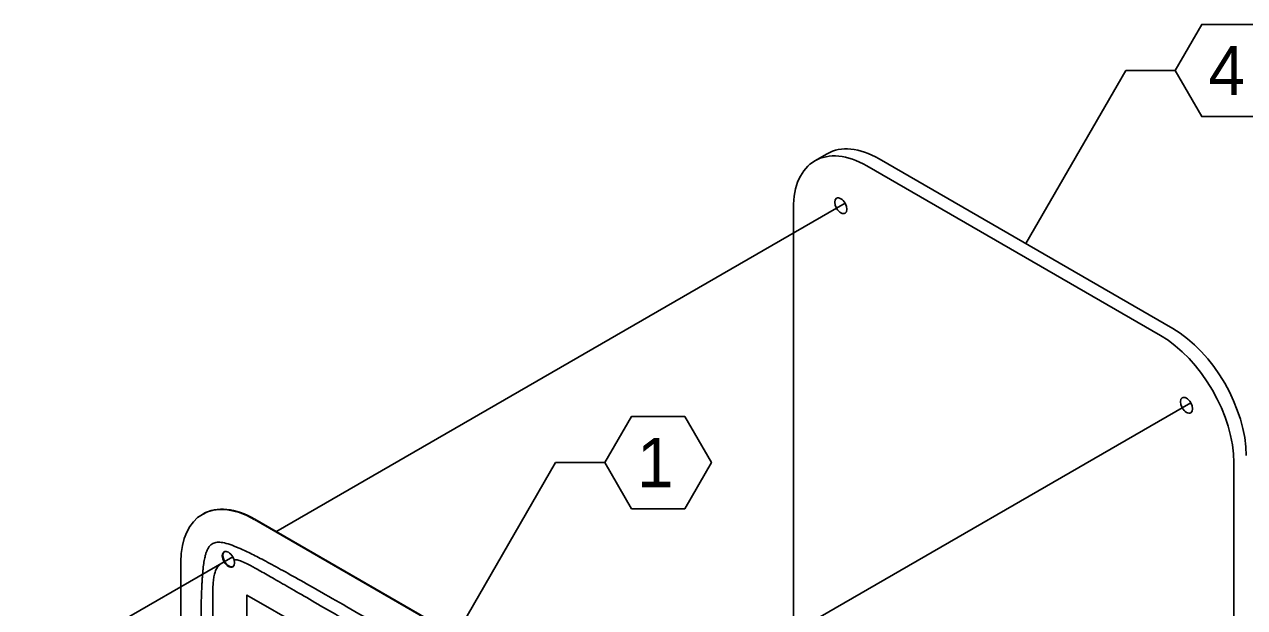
# Model space of a CAD drawing. Extents: x 99862 to 103151, y 100000 to 105076.
# Drawn here: x 102026.7 to 102423.3, y 104438.5 to 104628.1 of the extents above; entities that cross this region are included whole.
import ezdxf

# ---------------------------------------------------------------- set-up
doc = ezdxf.new("R2010")
doc.units = 0
for name, color, linetype in [('Level 15', 7, 'Continuous'), ('Level 16', 7, 'Continuous'), ('Level 20', 7, 'Continuous'), ('Level 40', 7, 'Continuous'), ('Level 41', 7, 'Continuous')]:
    doc.layers.add(name, color=color, linetype=linetype)

msp = doc.modelspace()

# ---------------------------------------------------------------- linework, layer by layer
at = {"layer": 'Level 15'}
for p, q in [((102352.18, 104556.8), (102384.68, 104613.09)), ((102400.68, 104613.09), (102384.68, 104613.09)), ((102166.84, 104429.34), (102199.34, 104485.63)), ((102215.34, 104485.63), (102199.34, 104485.63))]:
    msp.add_line(p, q, dxfattribs=at)
at = {"layer": 'Level 16'}
for p, q in [((102108.39, 104463.09), (102293.44, 104569.93)), ((102213.93, 104394.31), (102405.77, 104505.07)), ((102022.97, 104413.77), (102094.37, 104454.99))]:
    msp.add_line(p, q, dxfattribs=at)
at = {"layer": 'Level 20'}
for points in [[(102400.68, 104613.09), (102409.34, 104628.09), (102426.66, 104628.09), (102435.3, 104613.09), (102426.66, 104598.09), (102409.34, 104598.09), (102400.68, 104613.09)], [(102215.34, 104485.63), (102224, 104500.63), (102241.32, 104500.63), (102249.96, 104485.63), (102241.32, 104470.64), (102224, 104470.64), (102215.34, 104485.63)]]:
    msp.add_lwpolyline(points, dxfattribs=at)
at = {"layer": 'Level 40'}
for p, q in [((102101.4, 104467.12), (102196.86, 104412.01)), ((102101.6, 104467.24), (102197.05, 104412.13)), ((102077.53, 104223.34), (102077.53, 104453.35))]:
    msp.add_line(p, q, dxfattribs=at)
msp.add_lwpolyline([(102117.51, 104431.87), (102117.56, 104395.73), (102099.04, 104406.42), (102098.98, 104442.56), (102117.51, 104431.87)], dxfattribs=at)
for centre, major_axis, start_param, end_param in [((102101.4, 104439.57), (-16.88, 29.23), 5.497787, 7.068583), ((102101.6, 104439.68), (-16.88, 29.23), 5.497787, 6.283185), ((102093.16, 104454.3), (-1.41, 2.44), 0.07077, 3.070823)]:
    msp.add_ellipse(centre, major_axis=major_axis, ratio=0.57735, start_param=start_param, end_param=end_param, dxfattribs=at)
msp.add_ellipse((102092.96, 104454.18), major_axis=(-1.41, 2.44), ratio=0.57735, dxfattribs=at)
for points in [[(102195.29, 104401.92), (102147.57, 104429.48), (102099.84, 104457.04), (102083.93, 104466.22), (102083.93, 104447.85), (102083.93, 104332.85), (102083.93, 104217.84), (102083.93, 104199.47), (102099.84, 104190.29), (102147.57, 104162.73), (102195.29, 104135.17), (102211.2, 104125.99), (102211.2, 104144.36), (102211.2, 104259.36), (102211.2, 104374.37), (102211.2, 104381.33), (102207.2, 104388.86)], [(102091.55, 104453.37), (102087.9, 104451.41), (102087.9, 104445.56), (102087.9, 104424.84), (102087.9, 104404.13), (102147.57, 104369.68), (102207.23, 104335.24), (102207.23, 104355.95), (102207.23, 104376.66)], [(102207.23, 104376.66), (102207.23, 104390.44), (102195.29, 104397.33), (102147.57, 104424.89), (102099.84, 104452.44), (102097.18, 104453.98), (102094.78, 104454.07)]]:
    msp.add_open_spline(points, degree=4, dxfattribs=at)
at = {"layer": 'Level 41'}
for p, q in [((102287.57, 104586.03), (102283.59, 104583.73)), ((102399.91, 104529.24), (102304.45, 104584.35)), ((102300.47, 104582.06), (102395.93, 104526.94)), ((102276.6, 104568.28), (102276.6, 104338.27)), ((102419.79, 104485.61), (102419.79, 104255.6))]:
    msp.add_line(p, q, dxfattribs=at)
for centre, start_param, end_param in [((102304.45, 104556.8), 5.497787, 6.283185), ((102300.47, 104554.5), 6.283185, 7.068583), ((102300.47, 104554.5), 5.497787, 6.283185), ((102399.91, 104501.68), 3.926991, 5.497787), ((102395.93, 104499.39), 3.926991, 5.497787)]:
    msp.add_ellipse(centre, major_axis=(-16.88, 29.23), ratio=0.57735, start_param=start_param, end_param=end_param, dxfattribs=at)
for centre in [(102292.03, 104569.12), (102404.37, 104504.26)]:
    msp.add_ellipse(centre, major_axis=(-1.41, 2.44), ratio=0.57735, dxfattribs=at)

# ---------------------------------------------------------------- texts
at = {"layer": 'Level 20'}
for s, p in [('4', (102411.48, 104605.09)), ('1', (102225.79, 104477.63))]:
    msp.add_text(s, height=16, dxfattribs=at).set_placement(p)

doc.saveas('drawing.dxf')
